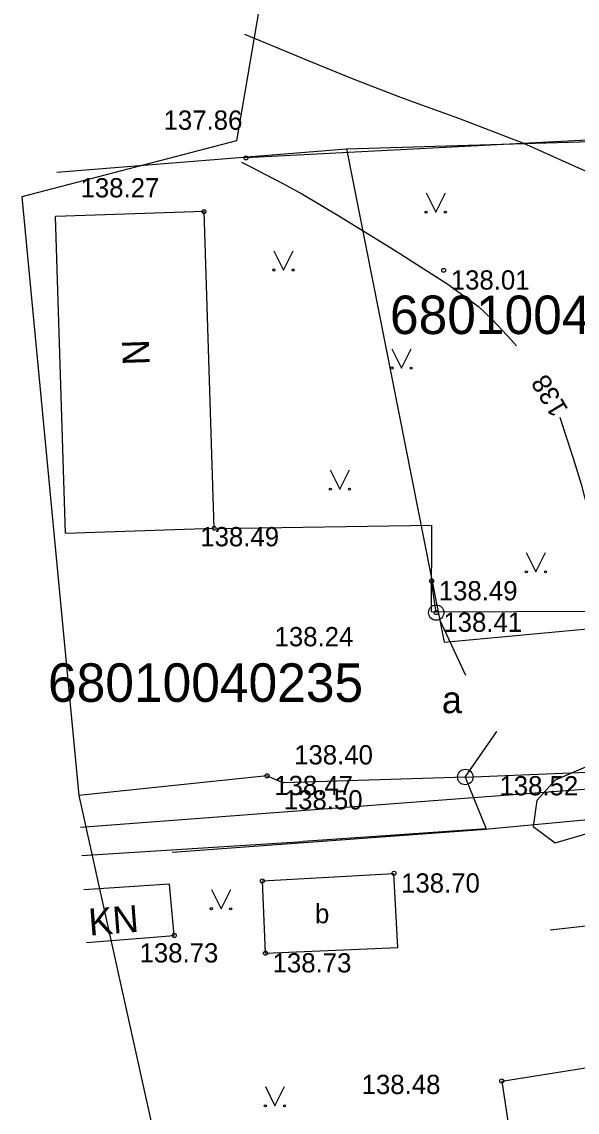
# Model space of a CAD drawing. Extents: x 728710 to 728960, y 272811 to 273475.
# Drawn here: x 728769.2 to 728783.61, y 273262.88 to 273291.2 of the extents above; entities that cross this region are included whole.
import ezdxf

# ---------------------------------------------------------------- set-up
doc = ezdxf.new("R2010")
doc.units = 0
for name, color, linetype in [('CELI_CMAL_####_####_#', 7, 'Continuous'), ('Level 28', 7, 'Continuous'), ('Level 3', 7, 'Continuous'), ('Level 30', 7, 'Continuous'), ('Level 4', 7, 'Continuous'), ('Level 42', 7, 'Continuous'), ('Level 43', 7, 'Continuous'), ('Level 48', 7, 'Continuous'), ('Level 50', 7, 'Continuous'), ('Level 51', 7, 'Continuous'), ('Level 52', 7, 'Continuous'), ('Level 57', 7, 'Continuous'), ('Level 58', 7, 'Continuous'), ('Level 59', 7, 'Continuous'), ('Level 8', 7, 'Continuous'), ('Level 9', 7, 'Continuous'), ('RAMI_UZMR_####_####_#', 7, 'Continuous'), ('ROBZ_KADS_####_TKST_#', 7, 'Continuous'), ('ROBZ_UZMR_####_####_#', 7, 'Continuous'), ('TERT_KONT_####_####_#', 7, 'Continuous')]:
    doc.layers.add(name, color=color, linetype=linetype)

msp = doc.modelspace()

# ---------------------------------------------------------------- linework, layer by layer
at = {"layer": 'CELI_CMAL_####_####_#'}
msp.add_lwpolyline([(728789.942, 273272.569), (728787.54, 273272.218), (728783.897, 273271.273), (728770.717, 273270.278)], dxfattribs=at)
at = {"layer": 'Level 28'}
for points in [[(728785.791, 273300.878), (728787.548, 273288.322), (728775.015, 273287.666)], [(728780.708, 273271.586), (728781.254, 273270.243), (728776.501, 273269.908)]]:
    msp.add_lwpolyline(points, dxfattribs=at)
at = {"layer": 'Level 3'}
for p, q in [((728773.925, 273286.272), (728770.066, 273286.148)), ((728770.331, 273277.924), (728770.066, 273286.148)), ((728774.19, 273278.048), (728773.925, 273286.272)), ((728770.331, 273277.924), (728774.19, 273278.048)), ((728773.03, 273268.807), (728770.804, 273268.66)), ((728773.153, 273267.471), (728773.03, 273268.807)), ((728770.878, 273267.29), (728773.153, 273267.471)), ((728781.655, 273263.689), (728783.825, 273264.036)), ((728781.655, 273263.689), (728782.101, 273260.719))]:
    msp.add_line(p, q, dxfattribs=at)
at = {"layer": 'Level 30'}
for points in [[(728789.177, 273280.628), (728788.542, 273281.773), (728787.644, 273283.44), (728786.554, 273285.152), (728785.346, 273286.434), (728783.906, 273287.292), (728782.228, 273288.044), (728780.542, 273288.689), (728779.081, 273289.221), (728777.822, 273289.708), (728776.653, 273290.183), (728775.674, 273290.591), (728774.985, 273290.877)], [(728774.9, 273287.556), (728775.158, 273287.425), (728775.523, 273287.24), (728775.97, 273287.006), (728776.478, 273286.727), (728777.421, 273286.166), (728778.844, 273285.29), (728780.229, 273284.401), (728781.054, 273283.806), (728781.395, 273283.475), (728781.672, 273283.186), (728781.886, 273282.952), (728782.039, 273282.787)], [(728783.16, 273280.931), (728783.299, 273280.503), (728783.5, 273279.891), (728783.715, 273279.196), (728783.893, 273278.522), (728784.037, 273277.819), (728784.172, 273277.057), (728784.286, 273276.371), (728784.367, 273275.893)]]:
    msp.add_lwpolyline(points, dxfattribs=at)
at = {"layer": 'Level 4'}
for p, q in [((728774.278, 273278.043), (728779.838, 273278.127)), ((728779.83, 273275.874), (728779.838, 273278.127)), ((728779.83, 273275.874), (728789.848, 273275.915)), ((728775.563, 273271.617), (728770.672, 273271.11)), ((728775.563, 273271.617), (728775.987, 273271.437)), ((728780.708, 273271.586), (728775.987, 273271.437))]:
    msp.add_line(p, q, dxfattribs=at)
for points in [[(728780.708, 273271.586), (728787.85, 273271.875), (728789.081, 273272.05), (728790.117, 273271.756), (728790.618, 273271.155)], [(728790.951, 273268.539), (728790.32, 273268.445), (728787.688, 273268.139), (728784.841, 273267.825), (728782.915, 273267.612)]]:
    msp.add_lwpolyline(points, dxfattribs=at)
at = {"layer": 'Level 42'}
msp.add_lwpolyline([(728778.361, 273363.303), (728780.185, 273349.821), (728787.396, 273299.393), (728788.824, 273288.687), (728789.966, 273279.612), (728789.68, 273278.991), (728788.986, 273278.539), (728787.225, 273277.322), (728786.051, 273275.933), (728786.004, 273273.362), (728785.463, 273272.543), (728783.043, 273271.508), (728782.567, 273270.973), (728782.471, 273270.304), (728783.044, 273269.874), (728783.9, 273270.126), (728785.092, 273270.261)], dxfattribs=at)
at = {"layer": 'Level 43'}
msp.add_line((728780.708, 273271.586), (728781.527, 273272.77), dxfattribs=at)
msp.add_circle((728780.708, 273271.586), 0.202, dxfattribs=at)
at = {"layer": 'Level 48'}
for centre, radius in [((728775.015, 273287.666), 0.05), ((728773.925, 273286.272), 0.05), ((728780.145, 273284.747), 0.05), ((728774.19, 273278.048), 0.05), ((728779.833, 273276.675), 0.0534), ((728779.953, 273275.857), 0.0534), ((728775.563, 273271.617), 0.0534), ((728778.855, 273269.084), 0.0534), ((728775.441, 273268.887), 0.0534), ((728773.153, 273267.471), 0.0534), ((728775.521, 273267.01), 0.0534), ((728781.655, 273263.689), 0.0534)]:
    msp.add_circle(centre, radius, dxfattribs=at)
at = {"layer": 'Level 52'}
msp.add_line((728780.038, 273275.676), (728780.717, 273274.23), dxfattribs=at)
msp.add_circle((728779.953, 273275.857), 0.2, dxfattribs=at)
at = {"layer": 'Level 8'}
msp.add_line((728779.953, 273275.857), (728779.833, 273276.675), dxfattribs=at)
msp.add_lwpolyline([(728770.756, 273269.552), (728776.501, 273269.908)], dxfattribs=at)
at = {"layer": 'Level 9'}
for p, q in [((728775.441, 273268.887), (728778.855, 273269.084)), ((728778.959, 273267.156), (728778.855, 273269.084)), ((728775.521, 273267.01), (728775.441, 273268.887)), ((728775.521, 273267.01), (728778.959, 273267.156))]:
    msp.add_line(p, q, dxfattribs=at)
at = {"layer": 'RAMI_UZMR_####_####_#'}
msp.add_lwpolyline([(728776.746, 273299.712), (728774.767, 273288.109), (728769.195, 273286.654), (728770.672, 273271.11), (728776.42, 273245.146), (728778.568, 273229.68), (728773.046, 273228.469), (728773.87, 273214.498), (728774.426, 273201.627), (728776.99, 273195.753), (728795.127, 273200.451), (728799.264, 273172.386), (728794.758, 273166.22), (728789.327, 273163.194), (728788.892, 273161.497), (728790.999, 273149.932)], dxfattribs=at)
at = {"layer": 'ROBZ_UZMR_####_####_#'}
for p, q in [((728777.622, 273287.903), (728787.847, 273288.205)), ((728770.1, 273287.293), (728777.622, 273287.903)), ((728777.622, 273287.903), (728780.162, 273275.086)), ((728780.162, 273275.086), (728789.505, 273275.973)), ((728781.127, 273270.22), (728790.169, 273271.078)), ((728773.095, 273269.638), (728781.127, 273270.22))]:
    msp.add_line(p, q, dxfattribs=at)
at = {"layer": 'TERT_KONT_####_####_#'}
for p, q in [((728779.69, 273286.757), (728779.94, 273286.257)), ((728779.94, 273286.257), (728780.19, 273286.757)), ((728775.739, 273285.255), (728775.989, 273284.755)), ((728775.989, 273284.755), (728776.239, 273285.255)), ((728778.804, 273282.71), (728779.054, 273282.21)), ((728779.054, 273282.21), (728779.304, 273282.71)), ((728777.204, 273279.563), (728777.454, 273279.063)), ((728777.454, 273279.063), (728777.704, 273279.563)), ((728782.291, 273277.418), (728782.541, 273276.918)), ((728782.541, 273276.918), (728782.791, 273277.418)), ((728774.117, 273268.665), (728774.367, 273268.165)), ((728774.367, 273268.165), (728774.617, 273268.665)), ((728775.517, 273263.545), (728775.767, 273263.045)), ((728775.767, 273263.045), (728776.017, 273263.545))]:
    msp.add_line(p, q, dxfattribs=at)
for centre, radius in [((728779.69, 273286.257), 0.028), ((728780.19, 273286.257), 0.0263), ((728775.739, 273284.755), 0.028), ((728776.239, 273284.755), 0.0263), ((728778.804, 273282.209), 0.028), ((728779.304, 273282.209), 0.0263), ((728777.203, 273279.063), 0.028), ((728777.703, 273279.063), 0.0263), ((728782.291, 273276.917), 0.028), ((728782.791, 273276.917), 0.0263), ((728774.117, 273268.165), 0.028), ((728774.617, 273268.165), 0.0263), ((728775.517, 273263.044), 0.028), ((728776.017, 273263.044), 0.0263)]:
    msp.add_circle(centre, radius, dxfattribs=at)

# ---------------------------------------------------------------- texts
at = {"layer": 'Level 50'}
msp.add_text('b', height=0.5, dxfattribs=at).set_placement((728776.807, 273267.788))
at = {"layer": 'Level 51'}
msp.add_text('138', height=0.5, rotation=121.028, dxfattribs=at).set_placement((728783.395, 273281.134))
at = {"layer": 'Level 57'}
for s, p in [(' 137.86', (728772.69, 273288.399)), (' 138.27', (728770.534, 273286.642)), (' 138.01', (728780.145, 273284.247)), (' 138.49', (728773.643, 273277.579)), (' 138.49', (728779.833, 273276.175)), (' 138.41', (728779.953, 273275.357)), (' 138.24', (728775.57, 273274.982)), (' 138.40', (728776.079, 273271.913)), (' 138.47', (728775.563, 273271.117)), (' 138.52', (728781.409, 273271.11)), (' 138.50', (728775.811, 273270.744)), (' 138.70', (728778.855, 273268.584)), (' 138.73', (728772.066, 273266.769)), (' 138.73', (728775.521, 273266.51)), (' 138.48', (728777.831, 273263.351))]:
    msp.add_text(s, height=0.5, dxfattribs=at).set_placement(p)
at = {"layer": 'Level 58'}
msp.add_text('a', height=0.7, dxfattribs=at).set_placement((728780.1, 273273.245))
at = {"layer": 'Level 59'}
for s, rotation, p in [('N', 271.847, (728771.794, 273282.942)), ('KN', 4.5392, (728770.955, 273267.465))]:
    msp.add_text(s, height=0.7, rotation=rotation, dxfattribs=at).set_placement(p)
at = {"layer": 'ROBZ_KADS_####_TKST_#'}
for s, p in [('68010040690', (728778.752, 273283.092)), ('68010040235', (728769.875, 273273.539))]:
    msp.add_text(s, height=1, dxfattribs=at).set_placement(p)

doc.saveas('drawing.dxf')
